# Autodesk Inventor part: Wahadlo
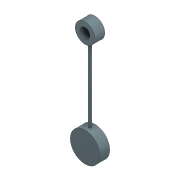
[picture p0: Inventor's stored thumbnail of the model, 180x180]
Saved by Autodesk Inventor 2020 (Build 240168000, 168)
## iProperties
Created: 2021-01
Part Number: Wahadlo
Material: Ołów
Document SubType Name: Modeling
Designer: Home
Mass: 112.895 g
Surface Area: 44.6323 cm^2
Volume: 9.95549 cm^3
Density: 11.34 g/cm^3
Appearance: Ołów
Author: Home
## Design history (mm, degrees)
sketch "Szkic1"
  geometry: C1 r 5 at (0, 0); C2 r 10 at (0, 0); C3 r 15 at (0, -100); 1 further point
  constraints: 3 centre point, 2 coincident, 1 vertical alignment
  dimensions: "d0" = 10 diameter of C1; "d1" = 20 diameter of C2; "d3" = 100 distance of C3.centre C1.centre; "d9" = 30 diameter of C3
extrude "Wyciągnięcie proste1" new body sketch "Szkic1" stored distance "d7" = 10; taper "d8" = 0 deg
sketch "Szkic2"
  geometry: C1 r 1.5 at (0, 0); 1 further point
  constraints: 1 centre point, 1 coincident
  dimensions: "d10" = 3 diameter of C1
extrude "Wyciągnięcie proste2" join sketch "Szkic2" stored distance "d11" = 10; taper "d12" = 0 deg
extrude "Wyciągnięcie proste3" cut sketch "Szkic1" extent not by distance; stored distance "d13" = 5; taper "d14" = 0 deg
node "Bryła1"
